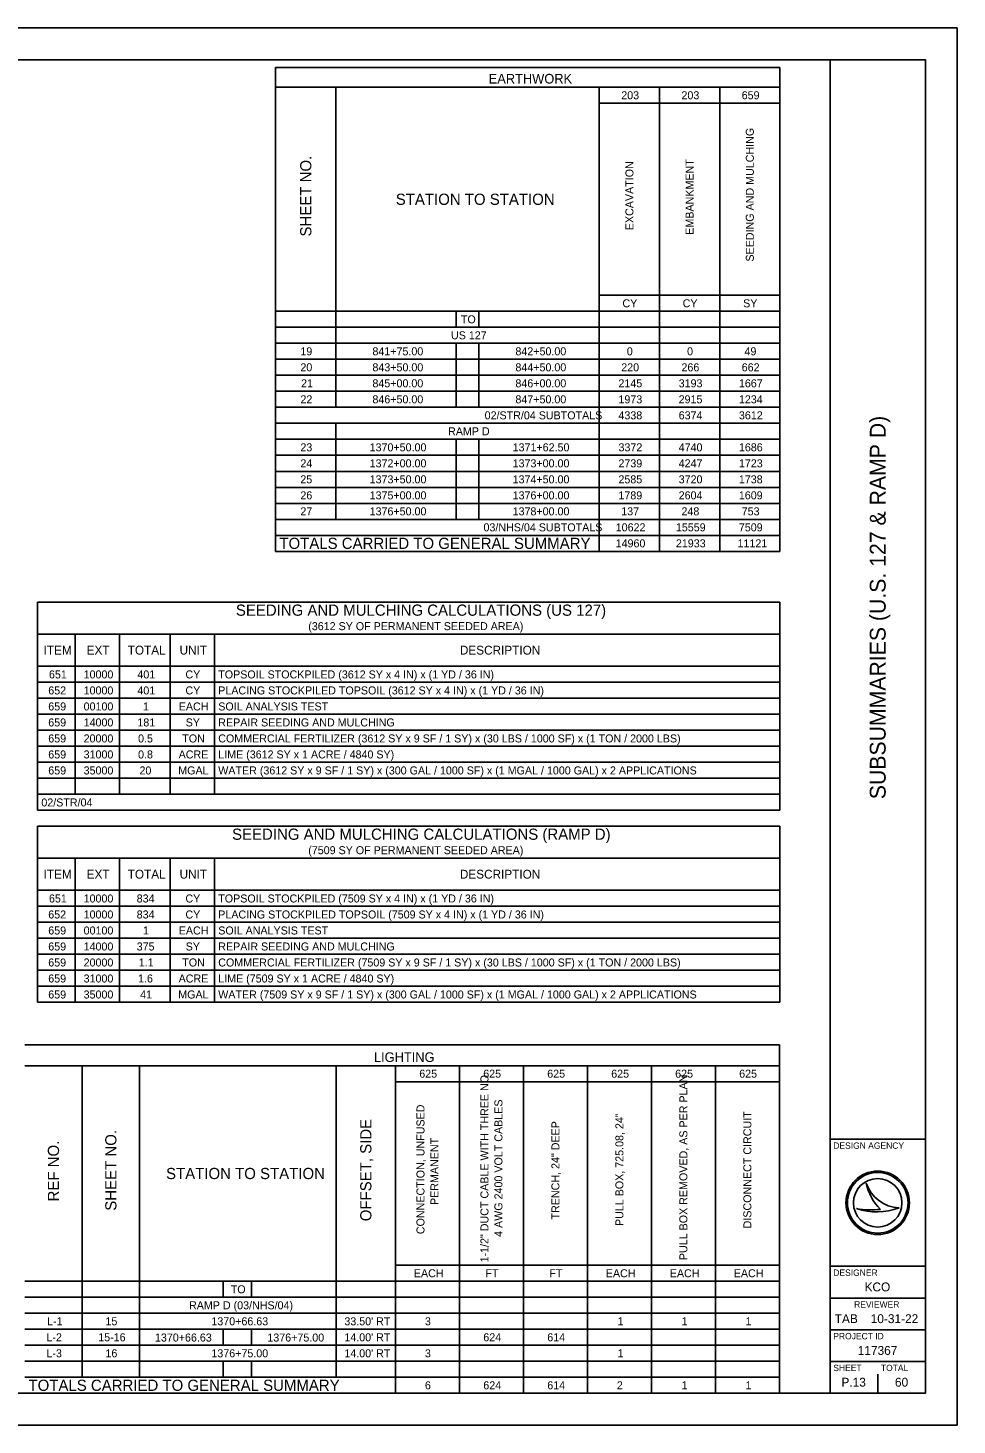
# Model space of a CAD drawing. Extents: x 0 to 34, y 0 to 22.
# Drawn here: x 19.36 to 34, y 0 to 22 of the extents above; entities that cross this region are included whole.
import ezdxf

# ---------------------------------------------------------------- set-up
doc = ezdxf.new("R2010")
doc.units = 0
for name, color, linetype in [('Default', 7, 'Continuous'), ('SH_Border', 7, 'Continuous'), ('SH_Cut_Line', 7, 'Continuous'), ('SH_Data', 7, 'Continuous')]:
    doc.layers.add(name, color=color, linetype=linetype)

msp = doc.modelspace()

# ---------------------------------------------------------------- linework, layer by layer
at = {"layer": 'Default'}
for p, q in [((23.264, 21.377), (31.209, 21.377)), ((23.264, 21.377), (23.264, 13.758)), ((31.209, 21.377), (31.209, 13.758)), ((23.264, 21.066), (31.209, 21.066)), ((24.213, 21.066), (24.213, 16.026)), ((28.363, 21.066), (28.363, 13.758)), ((29.312, 21.066), (29.312, 13.758)), ((30.261, 21.066), (30.261, 13.758)), ((28.363, 20.814), (31.209, 20.814)), ((28.363, 17.79), (31.209, 17.79)), ((23.264, 17.538), (31.209, 17.538)), ((26.11, 17.538), (26.11, 17.286)), ((26.466, 17.538), (26.466, 17.286)), ((23.264, 17.286), (31.209, 17.286)), ((23.264, 17.034), (31.209, 17.034)), ((26.11, 17.034), (26.11, 16.026)), ((26.466, 17.034), (26.466, 16.026)), ((23.264, 16.782), (31.209, 16.782)), ((23.264, 16.53), (31.209, 16.53)), ((23.264, 16.278), (31.209, 16.278)), ((23.264, 16.026), (31.209, 16.026)), ((23.264, 15.774), (31.209, 15.774)), ((24.213, 15.774), (24.213, 14.262)), ((23.264, 15.522), (31.209, 15.522)), ((26.11, 15.522), (26.11, 14.262)), ((26.466, 15.522), (26.466, 14.262)), ((23.264, 15.27), (31.209, 15.27)), ((23.264, 15.018), (31.209, 15.018)), ((23.264, 14.766), (31.209, 14.766)), ((23.264, 14.514), (31.209, 14.514)), ((23.264, 14.262), (31.209, 14.262)), ((23.264, 14.01), (31.209, 14.01)), ((23.264, 13.758), (31.209, 13.758)), ((19.514, 12.958), (31.209, 12.958)), ((19.514, 12.958), (19.514, 9.682)), ((31.209, 12.958), (31.209, 9.682)), ((19.514, 12.454), (31.209, 12.454)), ((20.107, 12.454), (20.107, 9.934)), ((20.803, 12.454), (20.803, 9.934)), ((21.604, 12.454), (21.604, 9.934)), ((22.301, 12.454), (22.301, 9.934)), ((19.514, 11.95), (31.209, 11.95)), ((19.514, 11.698), (31.209, 11.698)), ((19.514, 11.446), (31.209, 11.446)), ((19.514, 11.194), (31.209, 11.194)), ((19.514, 10.942), (31.209, 10.942)), ((19.514, 10.69), (31.209, 10.69)), ((19.514, 10.438), (31.209, 10.438)), ((19.514, 10.186), (31.209, 10.186)), ((19.514, 9.934), (31.209, 9.934)), ((19.514, 9.682), (31.209, 9.682)), ((19.514, 9.43), (31.209, 9.43)), ((19.514, 9.43), (19.514, 6.658)), ((31.209, 9.43), (31.209, 6.658)), ((19.514, 8.926), (31.209, 8.926)), ((20.107, 8.926), (20.107, 6.658)), ((20.803, 8.926), (20.803, 6.658)), ((21.604, 8.926), (21.604, 6.658)), ((22.301, 8.926), (22.301, 6.658)), ((19.514, 8.422), (31.209, 8.422)), ((19.514, 8.17), (31.209, 8.17)), ((19.514, 7.918), (31.209, 7.918)), ((19.514, 7.666), (31.209, 7.666)), ((19.514, 7.414), (31.209, 7.414)), ((19.514, 7.162), (31.209, 7.162)), ((19.514, 6.91), (31.209, 6.91)), ((19.514, 6.658), (31.209, 6.658)), ((19.312, 5.985), (31.2, 5.985)), ((31.2, 5.985), (31.2, 0.5)), ((19.312, 5.659), (31.2, 5.659)), ((20.216, 5.659), (20.216, 0.752)), ((21.12, 5.659), (21.12, 0.752)), ((24.218, 5.659), (24.218, 0.752)), ((25.152, 5.659), (25.152, 0.5)), ((26.16, 5.659), (26.16, 0.5)), ((27.168, 5.659), (27.168, 0.5)), ((28.176, 5.659), (28.176, 0.5)), ((29.184, 5.659), (29.184, 0.5)), ((30.192, 5.659), (30.192, 0.5)), ((25.152, 5.407), (31.2, 5.407)), ((25.152, 2.516), (31.2, 2.516)), ((19.312, 2.264), (31.2, 2.264)), ((22.439, 2.264), (22.439, 2.012)), ((22.884, 2.264), (22.884, 2.012)), ((19.312, 2.012), (31.2, 2.012)), ((19.312, 1.76), (31.2, 1.76)), ((19.312, 1.508), (31.2, 1.508)), ((22.439, 1.508), (22.439, 1.256)), ((22.884, 1.508), (22.884, 1.256)), ((19.312, 1.256), (31.2, 1.256)), ((19.312, 1.004), (31.2, 1.004)), ((22.439, 1.004), (22.439, 0.752)), ((22.884, 1.004), (22.884, 0.752)), ((19.312, 0.752), (31.2, 0.752)), ((19.312, 0.5), (31.2, 0.5))]:
    msp.add_line(p, q, dxfattribs=at)
at = {"layer": 'SH_Border'}
for p, q in [((32, 0.5), (32, 21.5)), ((32, 4.5), (33.5, 4.5)), ((32, 2.5), (33.5, 2.5)), ((32, 2), (33.5, 2)), ((32, 1.5), (33.5, 1.5)), ((32, 1), (33.5, 1))]:
    msp.add_line(p, q, dxfattribs=at)
msp.add_lwpolyline([(1.5, 21.5), (33.5, 21.5), (33.5, 0.5), (1.5, 0.5)], close=True, dxfattribs=at)
at = {"layer": 'SH_Cut_Line'}
msp.add_lwpolyline([(0, 0), (34, 0), (34, 22), (0, 22)], close=True, dxfattribs=at)
at = {"layer": 'SH_Data'}
for p, q in [((32.567, 3.81), (32.567, 3.81)), ((32.417, 3.41), (32.417, 3.41)), ((32.75, 3.5), (32.75, 3.5)), ((33.087, 3.419), (33.087, 3.419)), ((32.375, 0.675), (32.375, 0.675)), ((32.75, 0.5), (32.75, 0.8))]:
    msp.add_line(p, q, dxfattribs=at)
for radius in [0.5, 0.477, 0.477, 0.382]:
    msp.add_circle((32.75, 3.5), radius, dxfattribs=at)
for centre, radius, start, end in [((33.116, 3.998), 0.58, 198.9257, 198.9319), ((33.347, 3.97), 0.796, 191.6379, 191.6421), ((33.116, 3.998), 0.58, 198.9319, 267.1657), ((33.347, 3.97), 0.796, 191.6421, 226.0947), ((32.739, 4.37), 1.013, 251.4576, 290.0832), ((32.648, 4.654), 1.266, 259.4964, 259.4995), ((32.739, 4.37), 1.013, 251.4527, 251.4576), ((32.648, 4.654), 1.266, 259.4995, 276.6672)]:
    msp.add_arc(centre, radius, start, end, dxfattribs=at)

# ---------------------------------------------------------------- texts
at = {"layer": 'Default'}
for s, height, p in [('EARTHWORK', 0.1512, (26.621, 21.125)), ('203', 0.126, (28.709, 20.877)), ('203', 0.126, (29.658, 20.877)), ('659', 0.126, (30.607, 20.877)), ('STATION TO STATION', 0.1764, (25.157, 19.214)), ('CY', 0.126, (28.728, 17.601)), ('CY', 0.126, (29.677, 17.601)), ('SY', 0.126, (30.63, 17.601)), ('TO', 0.126, (26.183, 17.349)), ('US 127', 0.126, (26.027, 17.097)), ('19', 0.126, (23.654, 16.845)), ('841+75.00', 0.126, (24.789, 16.845)), ('842+50.00', 0.126, (27.042, 16.845)), ('0', 0.126, (28.797, 16.845)), ('0', 0.126, (29.746, 16.845)), ('49', 0.126, (30.651, 16.845)), ('20', 0.126, (23.654, 16.593)), ('843+50.00', 0.126, (24.789, 16.593)), ('844+50.00', 0.126, (27.042, 16.593)), ('220', 0.126, (28.709, 16.593)), ('266', 0.126, (29.658, 16.593)), ('662', 0.126, (30.607, 16.593)), ('21', 0.126, (23.665, 16.341)), ('845+00.00', 0.126, (24.789, 16.341)), ('846+00.00', 0.126, (27.042, 16.341)), ('2145', 0.126, (28.665, 16.341)), ('3193', 0.126, (29.614, 16.341)), ('1667', 0.126, (30.563, 16.341)), ('22', 0.126, (23.655, 16.089)), ('846+50.00', 0.126, (24.789, 16.089)), ('847+50.00', 0.126, (27.042, 16.089)), ('1973', 0.126, (28.665, 16.089)), ('2915', 0.126, (29.613, 16.089)), ('1234', 0.126, (30.563, 16.089)), ('02/STR/04 SUBTOTALS', 0.126, (26.557, 15.837)), ('4338', 0.126, (28.665, 15.837)), ('6374', 0.126, (29.614, 15.837)), ('3612', 0.126, (30.563, 15.837)), ('RAMP D', 0.126, (25.981, 15.585)), ('23', 0.126, (23.654, 15.333)), ('1370+50.00', 0.126, (24.745, 15.333)), ('1371+62.50', 0.126, (26.998, 15.333)), ('3372', 0.126, (28.666, 15.333)), ('4740', 0.126, (29.614, 15.333)), ('1686', 0.126, (30.563, 15.333)), ('24', 0.126, (23.654, 15.081)), ('1372+00.00', 0.126, (24.745, 15.081)), ('1373+00.00', 0.126, (26.998, 15.081)), ('2739', 0.126, (28.665, 15.081)), ('4247', 0.126, (29.614, 15.081)), ('1723', 0.126, (30.563, 15.081)), ('25', 0.126, (23.653, 14.829)), ('1373+50.00', 0.126, (24.745, 14.829)), ('1374+50.00', 0.126, (26.998, 14.829)), ('2585', 0.126, (28.665, 14.829)), ('3720', 0.126, (29.614, 14.829)), ('1738', 0.126, (30.562, 14.829)), ('26', 0.126, (23.654, 14.577)), ('1375+00.00', 0.126, (24.745, 14.577)), ('1376+00.00', 0.126, (26.998, 14.577)), ('1789', 0.126, (28.665, 14.577)), ('2604', 0.126, (29.614, 14.577)), ('1609', 0.126, (30.562, 14.577)), ('27', 0.126, (23.654, 14.325)), ('1376+50.00', 0.126, (24.745, 14.325)), ('1378+00.00', 0.126, (26.998, 14.325)), ('137', 0.126, (28.709, 14.325)), ('248', 0.126, (29.658, 14.325)), ('753', 0.126, (30.607, 14.325)), ('03/NHS/04 SUBTOTALS', 0.126, (26.539, 14.073)), ('10622', 0.126, (28.622, 14.073)), ('15559', 0.126, (29.57, 14.073)), ('7509', 0.126, (30.562, 14.073)), ('TOTALS CARRIED TO GENERAL SUMMARY', 0.1764, (23.323, 13.796)), ('14960', 0.126, (28.621, 13.821)), ('21933', 0.126, (29.57, 13.821)), ('11121', 0.126, (30.541, 13.821)), ('SEEDING AND MULCHING CALCULATIONS (US 127)', 0.1764, (22.638, 12.744)), ('(3612 SY OF PERMANENT SEEDED AREA)', 0.126, (23.778, 12.517)), ('ITEM', 0.1386, (19.609, 12.133)), ('EXT', 0.1386, (20.287, 12.133)), ('TOTAL', 0.1386, (20.934, 12.133)), ('UNIT', 0.1386, (21.751, 12.133)), ('DESCRIPTION', 0.1386, (26.167, 12.133)), ('651', 0.126, (19.693, 11.757)), ('10000', 0.126, (20.239, 11.757)), ('401', 0.126, (21.086, 11.757)), ('CY', 0.126, (21.843, 11.757)), ('TOPSOIL STOCKPILED (3612 SY x 4 IN) x (1 YD / 36 IN)', 0.126, (22.36, 11.757)), ('652', 0.126, (19.682, 11.505)), ('10000', 0.126, (20.239, 11.505)), ('401', 0.126, (21.086, 11.505)), ('CY', 0.126, (21.843, 11.505)), ('PLACING STOCKPILED TOPSOIL (3612 SY x 4 IN) x (1 YD / 36 IN)', 0.126, (22.36, 11.505)), ('659', 0.126, (19.682, 11.253)), ('00100', 0.126, (20.239, 11.253)), ('1', 0.126, (21.174, 11.253)), ('EACH', 0.126, (21.738, 11.253)), ('SOIL ANALYSIS TEST', 0.126, (22.36, 11.253)), ('659', 0.126, (19.682, 11.001)), ('14000', 0.126, (20.239, 11.001)), ('181', 0.126, (21.086, 11.001)), ('SY', 0.126, (21.847, 11.001)), ('REPAIR SEEDING AND MULCHING', 0.126, (22.36, 11.001)), ('659', 0.126, (19.682, 10.749)), ('20000', 0.126, (20.239, 10.749)), ('0.5', 0.126, (21.097, 10.749)), ('TON', 0.126, (21.793, 10.749)), ('COMMERCIAL FERTILIZER (3612 SY x 9 SF / 1 SY) x (30 LBS / 1000 SF) x (1 TON / 2000 LBS)', 0.126, (22.36, 10.749)), ('659', 0.126, (19.682, 10.497)), ('31000', 0.126, (20.239, 10.497)), ('0.8', 0.126, (21.097, 10.497)), ('ACRE', 0.126, (21.736, 10.497)), ('LIME (3612 SY x 1 ACRE / 4840 SY)', 0.126, (22.36, 10.497)), ('659', 0.126, (19.682, 10.245)), ('35000', 0.126, (20.239, 10.245)), ('20', 0.126, (21.119, 10.245)), ('MGAL', 0.126, (21.73, 10.245)), ('WATER (3612 SY x 9 SF / 1 SY) x (300 GAL / 1000 SF) x (1 MGAL / 1000 GAL) x 2 APPLICATIONS', 0.126, (22.36, 10.245)), ('02/STR/04', 0.126, (19.573, 9.741)), ('SEEDING AND MULCHING CALCULATIONS (RAMP D)', 0.1764, (22.578, 9.216)), ('(7509 SY OF PERMANENT SEEDED AREA)', 0.126, (23.778, 8.989)), ('ITEM', 0.1386, (19.609, 8.605)), ('EXT', 0.1386, (20.287, 8.605)), ('TOTAL', 0.1386, (20.934, 8.605)), ('UNIT', 0.1386, (21.751, 8.605)), ('DESCRIPTION', 0.1386, (26.167, 8.605)), ('TOPSOIL STOCKPILED (7509 SY x 4 IN) x (1 YD / 36 IN)', 0.126, (22.36, 8.229)), ('651', 0.126, (19.693, 8.229)), ('10000', 0.126, (20.239, 8.229)), ('834', 0.126, (21.075, 8.229)), ('CY', 0.126, (21.843, 8.229)), ('652', 0.126, (19.682, 7.977)), ('10000', 0.126, (20.239, 7.977)), ('834', 0.126, (21.075, 7.977)), ('CY', 0.126, (21.843, 7.977)), ('PLACING STOCKPILED TOPSOIL (7509 SY x 4 IN) x (1 YD / 36 IN)', 0.126, (22.36, 7.977)), ('659', 0.126, (19.682, 7.725)), ('00100', 0.126, (20.239, 7.725)), ('1', 0.126, (21.174, 7.725)), ('EACH', 0.126, (21.738, 7.725)), ('SOIL ANALYSIS TEST', 0.126, (22.36, 7.725)), ('659', 0.126, (19.682, 7.473)), ('14000', 0.126, (20.239, 7.473)), ('375', 0.126, (21.075, 7.473)), ('SY', 0.126, (21.847, 7.473)), ('REPAIR SEEDING AND MULCHING', 0.126, (22.36, 7.473)), ('659', 0.126, (19.682, 7.221)), ('20000', 0.126, (20.239, 7.221)), ('1.1', 0.126, (21.108, 7.221)), ('TON', 0.126, (21.793, 7.221)), ('COMMERCIAL FERTILIZER (7509 SY x 9 SF / 1 SY) x (30 LBS / 1000 SF) x (1 TON / 2000 LBS)', 0.126, (22.36, 7.221)), ('659', 0.126, (19.682, 6.969)), ('31000', 0.126, (20.239, 6.969)), ('1.6', 0.126, (21.097, 6.969)), ('ACRE', 0.126, (21.736, 6.969)), ('LIME (7509 SY x 1 ACRE / 4840 SY)', 0.126, (22.36, 6.969)), ('659', 0.126, (19.682, 6.717)), ('35000', 0.126, (20.239, 6.717)), ('41', 0.126, (21.13, 6.717)), ('MGAL', 0.126, (21.73, 6.717)), ('WATER (7509 SY x 9 SF / 1 SY) x (300 GAL / 1000 SF) x (1 MGAL / 1000 GAL) x 2 APPLICATIONS', 0.126, (22.36, 6.717)), ('LIGHTING', 0.1512, (24.813, 5.718)), ('625', 0.126, (25.527, 5.47)), ('625', 0.126, (26.535, 5.47)), ('625', 0.126, (27.543, 5.47)), ('625', 0.126, (28.551, 5.47)), ('625', 0.126, (29.559, 5.47)), ('625', 0.126, (30.567, 5.47)), ('STATION TO STATION', 0.1764, (21.538, 3.873)), ('EACH', 0.126, (25.442, 2.327)), ('FT', 0.126, (26.569, 2.327)), ('FT', 0.126, (27.577, 2.327)), ('EACH', 0.126, (28.466, 2.327)), ('EACH', 0.126, (29.474, 2.327)), ('EACH', 0.126, (30.482, 2.327)), ('TO', 0.126, (22.557, 2.075)), ('RAMP D (03/NHS/04)', 0.126, (21.9, 1.823)), ('L-1', 0.126, (19.664, 1.571)), ('15', 0.126, (20.583, 1.571)), ('1370+66.63', 0.126, (22.252, 1.571)), ("33.50' RT", 0.126, (24.347, 1.571)), ('3', 0.126, (25.616, 1.571)), ('1', 0.126, (28.651, 1.571)), ('1', 0.126, (29.659, 1.571)), ('1', 0.126, (30.667, 1.571)), ('L-2', 0.126, (19.653, 1.319)), ('15-16', 0.126, (20.469, 1.319)), ('1370+66.63', 0.126, (21.363, 1.315)), ('1376+75.00', 0.126, (23.134, 1.315)), ("14.00' RT", 0.126, (24.347, 1.319)), ('624', 0.126, (26.536, 1.319)), ('614', 0.126, (27.544, 1.319)), ('L-3', 0.126, (19.653, 1.067)), ('16', 0.126, (20.583, 1.067)), ('1376+75.00', 0.126, (22.252, 1.067)), ("14.00' RT", 0.126, (24.347, 1.067)), ('3', 0.126, (25.616, 1.067)), ('1', 0.126, (28.651, 1.067)), ('TOTALS CARRIED TO GENERAL SUMMARY', 0.1764, (19.371, 0.538)), ('6', 0.126, (25.616, 0.563)), ('624', 0.126, (26.536, 0.563)), ('614', 0.126, (27.544, 0.563)), ('2', 0.126, (28.64, 0.563)), ('1', 0.126, (29.659, 0.563)), ('1', 0.126, (30.667, 0.563))]:
    msp.add_text(s, height=height, dxfattribs=at).set_placement(p)
for s, height, p in [('SEEDING AND MULCHING', 0.126, (30.798, 18.321)), ('SHEET NO.', 0.1764, (23.827, 18.716)), ('EXCAVATION', 0.126, (28.901, 18.815)), ('EMBANKMENT', 0.126, (29.849, 18.744)), ('1-1/2" DUCT CABLE WITH THREE NO. ', 0.126, (26.617, 2.561)), ('PULL BOX REMOVED, AS PER PLAN', 0.126, (29.751, 2.597)), ('4 AWG 2400 VOLT CABLES', 0.126, (26.837, 2.963)), ('CONNECTION, UNFUSED ', 0.126, (25.609, 3.006)), ('PULL BOX, 725.08, 24"', 0.126, (28.743, 3.134)), ('DISCONNECT CIRCUIT', 0.126, (30.759, 3.097)), ('SHEET NO.', 0.1764, (20.756, 3.375)), ('OFFSET, SIDE', 0.1764, (24.773, 3.209)), ('TRENCH, 24" DEEP', 0.126, (27.735, 3.237)), ('REF NO.', 0.1764, (19.852, 3.521)), ('PERMANENT', 0.126, (25.829, 3.465))]:
    msp.add_text(s, height=height, rotation=90, dxfattribs=at).set_placement(p)
at = {"layer": 'SH_Data'}
msp.add_text('SUBSUMMARIES (U.S. 127 & RAMP D)', height=0.25, rotation=90, dxfattribs=at).set_placement((32.875, 9.855))
for s, height, p in [('DESIGN AGENCY', 0.1, (32.05, 4.35)), ('DESIGNER', 0.1, (32.05, 2.35)), ('KCO', 0.14, (32.542, 2.105)), ('REVIEWER', 0.1, (32.378, 1.85)), ('TAB', 0.14, (32.072, 1.605)), ('10-31-22', 0.14, (32.639, 1.605)), ('PROJECT ID', 0.1, (32.05, 1.35)), ('117367', 0.14, (32.435, 1.105)), ('SHEET', 0.1, (32.05, 0.85)), ('TOTAL', 0.1, (32.8, 0.85)), ('P.13', 0.14, (32.178, 0.605)), ('60', 0.14, (33.021, 0.605))]:
    msp.add_text(s, height=height, dxfattribs=at).set_placement(p)

doc.saveas('drawing.dxf')
